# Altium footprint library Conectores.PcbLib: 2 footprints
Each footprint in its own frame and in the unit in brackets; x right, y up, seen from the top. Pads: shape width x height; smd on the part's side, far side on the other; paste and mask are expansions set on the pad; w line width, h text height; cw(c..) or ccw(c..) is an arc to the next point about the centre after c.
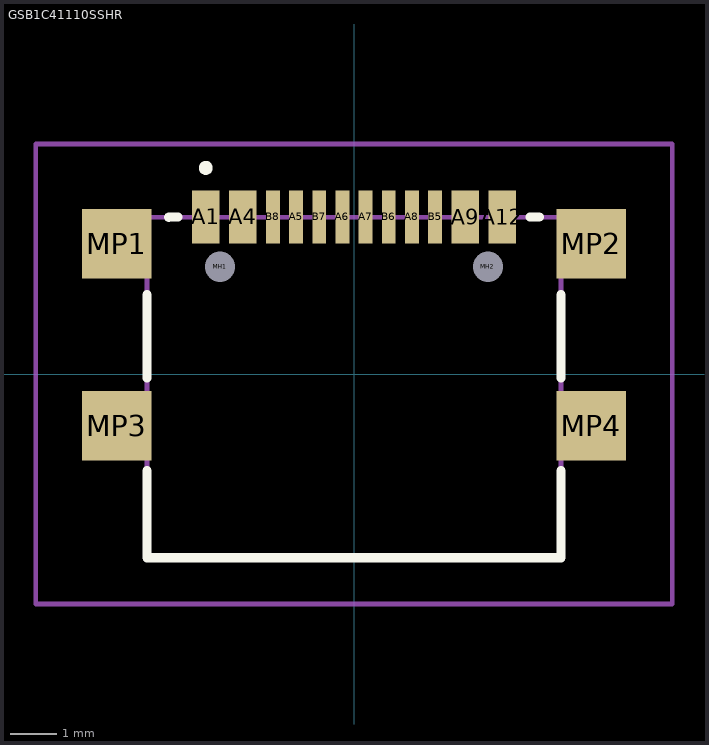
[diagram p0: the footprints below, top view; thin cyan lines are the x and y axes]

## GSB1C41110SSHR [mm]
pads (18):
  rect 0.6x1.15 smd: A1(-3.2,3.39) A4(-2.4,3.39) A9(2.4,3.39) A12(3.2,3.39)
  rect 0.3x1.15 smd: A5(-1.25,3.39) A6(-0.25,3.39) A7(0.25,3.39) A8(1.25,3.39) B5(1.75,3.39) B6(0.75,3.39) B7(-0.75,3.39) B8(-1.75,3.39)
  round 0.325 hole 0.65 unplated: MH1(-2.89,2.315) MH2(2.89,2.315)
  rect 1.5x1.5 smd: MP1(-5.12,2.815) MP2(5.12,2.815) MP3(-5.12,-1.115) MP4(5.12,-1.115)
Top Overlay:
  lines w0.2: -4.47,-2.088 -4.47,-3.965 4.47,-3.965 4.47,-2.088 ; -4.47,-0.088 -4.47,1.712 ; -4,3.385 -3.8,3.39 ; 3.8,3.39 4,3.39 ; 4.47,-0.088 4.47,1.712 ; -3.2,4.4 cw(c-3.2,4.45) -3.2,4.5 ; -3.2,4.4 ccw(c-3.2,4.45) -3.2,4.5 ; -3.2,4.4 cw(c-3.2,4.45) -3.2,4.5
Mechanical 13:
  lines w0.1: -4.47,-3.965 -4.47,3.385 4.47,3.385 4.47,-3.965 -4.47,-3.965
Mechanical 15:
  lines w0.1: -6.87,-4.965 -6.87,4.965 6.87,4.965 6.87,-4.965 -6.87,-4.965
3D body "GSB1C41110SSHR.stp": height 3.12, standoff -0.76, extent -5.67,-4.088 5.67,3.51

## PCBComponent_1 [mm]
